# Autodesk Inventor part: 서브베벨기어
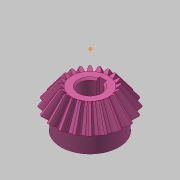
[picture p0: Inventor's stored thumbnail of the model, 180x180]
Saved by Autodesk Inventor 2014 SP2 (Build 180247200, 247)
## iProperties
Created: 2018-09
Part Number: 서브베벨기어
Material: 강철, 탄소
Document SubType Name: Modeling
Categories: <?xml version="1.0" encoding="UTF-16"?> <MemberInstance><Categories><FamilyTemplate><FamilyTemplateParameter ValueType="xs:double" Id="1" ObjectReferenceKey="da
Mass: 135.037 g
Surface Area: 63.6444 cm^2
Volume: 17.1585 cm^3
Density: 7.87 g/cm^3
Appearance: 분홍색
CustomPartVersion: 1
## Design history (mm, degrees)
node "맨 위 점"
node "메쉬 평면2"
sketch "톱니 본체 스케치"
  geometry: L1 (0, 0)-(18.003, -31.331); L2 (18.003, -31.331)-(21.664, -28.891); L3 (21.664, -28.891)-(0, 0); L4 (20, -30)-(0, 0); L5 (10.813, -18.818)-(13.012, -17.352); L6 (18.003, -31.331)-(10.813, -18.818); L7 (21.664, -28.891)-(13.012, -17.352); L8 (0, -39.387)-(0, 6.564) reference; L9 (0, -30)-(21.664, -30)
  constraints: 16 end point, 4 point on line, 3 perpendicular, 2 collinear, 1 horizontal alignment, 1 vertical alignment
  dimensions: "d0" = 40 diameter of L4.start L8 (= da_de); "d1" = 36.00616 diameter of L1.end L8 (= da_dfe); "d2" = 43.3282 diameter of L2.end L8 (= da_dae); "d3" = 14.4 distance between parallel lines of L2 L5 (= da_b); "d4" = 28.8906 vertical distance of L2.end L1.start (= da_ve)
revolve "톱니 본체" sketch "톱니 본체 스케치" stored, may be unused: angle "d5" = 90 deg
node "시작점"
node "톱니 평면"
sketch "시작 스케치"
  geometry: L1 (0, -23.505)-(0, 10.645) reference; L2 (-0.834, -2.928)-(0.834, -2.928); A1 r 8.898 centre (-9.698, -3.713) between (-0.834, -2.928) and (-3.903, 3.04); A2 r 8.898 centre (9.698, -3.713) between (3.903, 3.04) and (0.834, -2.928); A3 r 27.357 centre (0, -24.037) between (3.903, 3.04) and (-3.903, 3.04); 1 further point
  constraints: 6 point on circle, 3 centre point, 3 symmetric about line, 2 end point, 1 coincident, 1 perpendicular, 1 other
  dimensions: "d7" = 8.89846 radius of A1 (= fd_rr); "d8" = 9.69794 horizontal distance of point (0, -24.037) A1.centre (= fd_x); "d9" = 20.32439 vertical distance of point (0, -24.037) A1.centre (= fd_y); "d57" = 27.35701 radius of A3 (= 0.5 x fd_dva + 0.3 x da_he); "d58" = 21.10901 distance from line of A3.centre L2 (= 0.5 x fd_dva - 1.12 x da_he)
node "끝점"
  node "끝 평면"
sketch "3D 스케치 오른쪽"
  node "Helical Curve Right" dims "d65" = 229.90621 (computed from da_dm, da_delta, da_beta), "d66" = 31.5, "d67" = 40 (= da_de), "d68" = -5.88003 (= -da_delta), "d69" = 12.16458 (computed from fd_loft, da_delta)
node "끝 평면 오른쪽"
sketch "끝 스케치 오른쪽"
  geometry: L1 (0, -22.649)-(0, 12.15) reference; L2 (-0.497, -1.72)-(0.497, -1.72); A1 r 5.299 centre (-5.775, -2.187) between (-0.497, -1.72) and (-2.324, 1.834); A2 r 5.299 centre (5.775, -2.187) between (2.324, 1.834) and (0.497, -1.72); A3 r 16.291 centre (0, -14.29) between (2.324, 1.834) and (-2.324, 1.834); 1 further point
  constraints: 6 point on circle, 3 centre point, 3 symmetric about line, 2 end point, 1 coincident, 1 perpendicular, 1 other
  dimensions: "d70" = 5.77526 horizontal distance of A3.centre A1.centre (computed from fd_x, fd_ratio); "d71" = 12.10346 vertical distance of point (0, -14.29) A1.centre (computed from fd_y, fd_ratio); "d72" = 5.29916 radius of A1 (computed from fd_rr, fd_ratio); "d73" = 12.57071 distance from line of point (0, -14.29) L2 (computed from d58, fd_ratio); "d74" = 16.29149 radius of A3 (computed from d57, fd_ratio)
feature "로프트 오른쪽" sketch "끝 스케치 오른쪽" dims "d75" = 0, "d77" = 0, "d79" = 0, "d80" = 90 deg, "d85" = 20, "d92" = 90 deg, "d93" = 90 deg, "da_teethtype" = 0 [user parameter]
sketch "3D 스케치 왼쪽"
  node "Helical Curve Left" dims "d26" = 229.90621 (computed from da_dm, da_delta, da_beta), "d27" = 12.16458 (computed from fd_loft, da_delta), "d28" = 40 (= da_de), "d29" = -5.88003 (= -da_delta)
node "끝 평면 왼쪽"
sketch "끝 스케치 왼쪽" dims "d56" = 10.82768 (derived)
  geometry: L1 (0, -35.087)-(0, 18.089) reference; L2 (-0.497, -1.716)-(0.497, -1.716); A1 r 5.299 centre (-5.775, -2.183) between (-0.497, -1.716) and (-2.324, 1.838); A2 r 5.299 centre (5.775, -2.183) between (2.324, 1.838) and (0.497, -1.716); A3 r 16.291 centre (0, -14.287) between (2.324, 1.838) and (-2.324, 1.838); 2 further points; 1 other entity
  constraints: 6 point on circle, 3 centre point, 3 symmetric about line, 2 end point, 1 coincident, 2 other
  dimensions: "d30" = 5.29916 radius of A1 (computed from fd_rr, fd_ratio); "d31" = 5.77526 horizontal distance of point (0, -14.287) A1.centre (computed from fd_x, fd_ratio); "d32" = 12.10346 vertical distance of A1.centre point (0, -14.287) (computed from fd_y, fd_ratio); "d61" = 16.29149 radius of A3 (computed from d57, fd_ratio); "d62" = 12.57071 distance from line of point (0, -14.287) L2 (computed from d58, fd_ratio)
feature "로프트 왼쪽" sketch "끝 스케치 왼쪽" dims "d35" = 0, "d37" = 0, "d39" = 0, "d40" = 90 deg, "d84" = 10, "d90" = 90 deg, "d91" = 90 deg, "da_teethtype" = 0 [user parameter]
sketch "본체 스케치"
  geometry: L1 (0, -35.038)-(0, -19.531) reference; L2 (18.003, -31.331)-(10.813, -18.818) reference; L3 (10.813, -18.818)-(0, -18.818); L4 (18.003, -31.331)-(0, -31.331)
  constraints: 4 end point, 2 perpendicular, 2 point on line
revolve "본체 고정" sketch "본체 스케치" stored, may be unused: angle "d46" = 90 deg
feature "피치 지름" dims angle "d47" = 90 deg
sketch "스케치8"
  geometry: C1 r 17 at (0, 0); 1 further point
  constraints: 1 centre point, 1 coincident
  dimensions: "d94" = 34 diameter of C1
extrude "돌출1" join sketch "스케치8" distance "d95" = 10; taper "d96" = 0 deg
sketch "스케치9"
  geometry: 1 further point
hole "구멍1" sketch "스케치9" at (0, 0) diameter "d97" = 12; stored, may be unused: countersink angle "d101" = 90 deg, drill point angle "d103" = 118 deg; dims "d98" = 6, "d99" = 4, "d100" = 2, "d102" = 8
sketch "스케치10"
  geometry: 1 further point
sketch "스케치11"
  geometry: 1 further point
sketch "스케치12"
  geometry: L1 (-2, 5.657)-(-2, 7.8); L2 (-2, 7.8)-(2, 7.8); L3 (2, 7.8)-(2, 5.657); A1 r 6 centre (0, 0) between (-2, 5.657) and (2, 5.657) reference; 1 further point
  constraints: 6 end point, 2 parallel, 2 point on circle, 1 perpendicular, 1 vertical
  dimensions: "d104" = 4 distance of L1.end L2.end; "d105" = 13.8 dimension on A1 L2
extrude "돌출2" cut sketch "스케치12" stored distance "d106" = 7; taper "d107" = 0 deg
chamfer "모따기1" distance "d108" = 1; stored, may be unused: second distance "d109" = 2, angle "d110" = 45 deg
body "Solid1"
feature "로프트" dims "d17" = 0, "d18" = 90 deg, "d19" = 0, "d20" = 90 deg, "d89" = 0, "da_teethtype" = 0 [user parameter]
pattern_circular "원형 패턴" dims angle "d22" = 360 deg, "d88" = 0, "da_teethtype" = 0 [user parameter]
pattern_circular "원형 패턴 오른쪽" dims angle "d82" = 360 deg, "da_teethtype" = 0 [user parameter]
pattern_circular "원형 패턴 왼쪽" dims angle "d42" = 360 deg, "da_teethtype" = 0 [user parameter]
sketch "끝 스케치"
  geometry: L1 (0, -15.359)-(0, 6.983) reference; L2 (-0.497, -1.72)-(0.497, -1.72); A1 r 5.299 centre (-5.775, -2.187) between (-0.497, -1.72) and (-2.324, 1.834); A2 r 5.299 centre (5.775, -2.187) between (2.324, 1.834) and (0.497, -1.72); A3 r 16.291 centre (0, -14.29) between (2.324, 1.834) and (-2.324, 1.834); 1 further point
  constraints: 6 point on circle, 3 centre point, 3 symmetric about line, 2 end point, 1 coincident, 1 other
  dimensions: "d12" = 5.29916 radius of A1 (computed from fd_rr, fd_ratio); "d15" = 5.77526 horizontal distance of A1.centre point (0, -14.29) (computed from fd_x, fd_ratio); "d16" = 12.10346 vertical distance of A1.centre point (0, -14.29) (computed from fd_y, fd_ratio); "d59" = 16.29149 radius of A3 (computed from d57, fd_ratio); "d60" = 12.57071 distance from line of A3.centre L2 (computed from d58, fd_ratio)
sketch "Sketch6"
  geometry: L1 (20, -30)-(0, 0) reference; L2 (0, -37.8)-(0, 6.3) reference
body "Srf1"
other parameters: "da_b" = 14.4 [user parameter; used in 2 equation terms], "da_de" = 40 [user parameter; used in 4 equation terms], "da_dae" = 43.3282 [user parameter; used in 2 equation terms], "da_dfe" = 36.00616 [user parameter; used in 1 equation term], "da_le" = 36.05551 [user parameter; used in 1 equation term], "da_omega" = 90 deg [user parameter; used in 1 equation term], "da_beta" = 0 [user parameter; used in 2 equation terms], "da_delta" = 5.88003 [user parameter; used in 8 equation terms], "da_alpha" = 20 deg [user parameter; used in 2 equation terms], "da_he" = 4.4 [user parameter; used in 4 equation terms], "da_ve" = 28.8906 [user parameter; used in 1 equation term], "fd_dv" = 48.07402 (computed from da_de, da_delta) [user parameter; used in 1 equation term], "fd_dva" = 52.07402 (computed from da_dae, da_delta) [user parameter; used in 3 equation terms], "fd_dvb" = 45.1748 (computed from fd_dv, da_alpha) [user parameter; used in 2 equation terms], "da_zv" = 240.37008 [user parameter; used in 1 equation term], "fd_loft" = 14.62 (= da_b + 0.05 x da_he) [user parameter; used in 4 equation terms], "fd_ratio" = 5.95514 (computed from da_le, fd_loft) [user parameter; used in 15 equation terms], "fd_rr" = 8.89846 (computed from fd_dd, fd_dvb) [user parameter; used in 6 equation terms], "fd_angle" = 0.66075 (computed from da_zv) [user parameter; used in 4 equation terms], "fd_x1" = 1.58709 (computed from da_dvw, fd_angle) [user parameter; used in 1 equation term], "fd_y1" = 23.98456 (computed from da_dvw, fd_angle) [user parameter; used in 1 equation term], "fd_x2" = 8.11084 (computed from fd_rr, fd_angle2, fd_angle) [user parameter; used in 1 equation term], "fd_y2" = 3.66016 (computed from fd_rr, fd_angle2, fd_angle) [user parameter; used in 1 equation term], "fd_x" = 9.69794 (= fd_x1 + fd_x2) [user parameter; used in 4 equation terms], "fd_y" = 20.32439 (= fd_y1 - fd_y2) [user parameter; used in 4 equation terms], "fd_angle2" = 3.57832 (computed from fd_dvb, fd_dd, da_alpha) [user parameter; used in 2 equation terms], "fd_dd" = 48.55402 (= fd_dva - 0.8 x da_he) [user parameter; used in 2 equation terms], "da_dvw" = 48.07402 [user parameter; used in 2 equation terms], "d11" = 14.62 (= fd_loft), "da_dm" = 32.01232 [user parameter; used in 2 equation terms], "da_x" = 0 [user parameter], "da_m" = 2 [user parameter], "d48" = 0, "d49" = 0, "d50" = 90 deg (= da_omega), "d51" = 9 deg (computed from da_z), "d52" = 0, "d53" = 0, "d54" = 0
